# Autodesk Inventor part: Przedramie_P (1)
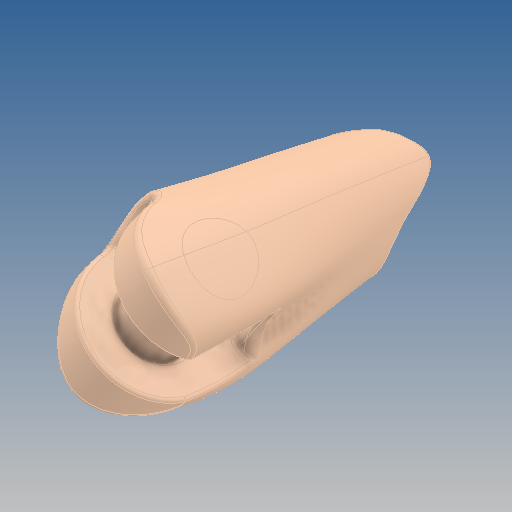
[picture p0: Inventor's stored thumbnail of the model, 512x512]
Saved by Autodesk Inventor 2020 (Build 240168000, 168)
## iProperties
Created: 2019-10
Part Number: Przedramie_P (1)
Material: GFRP
Document SubType Name: Modeling
Designer: yello
Density: 1.75 g/cm^3
Appearance: Default
Author: yello
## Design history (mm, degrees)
feature "Body1"
body "Solid1"
